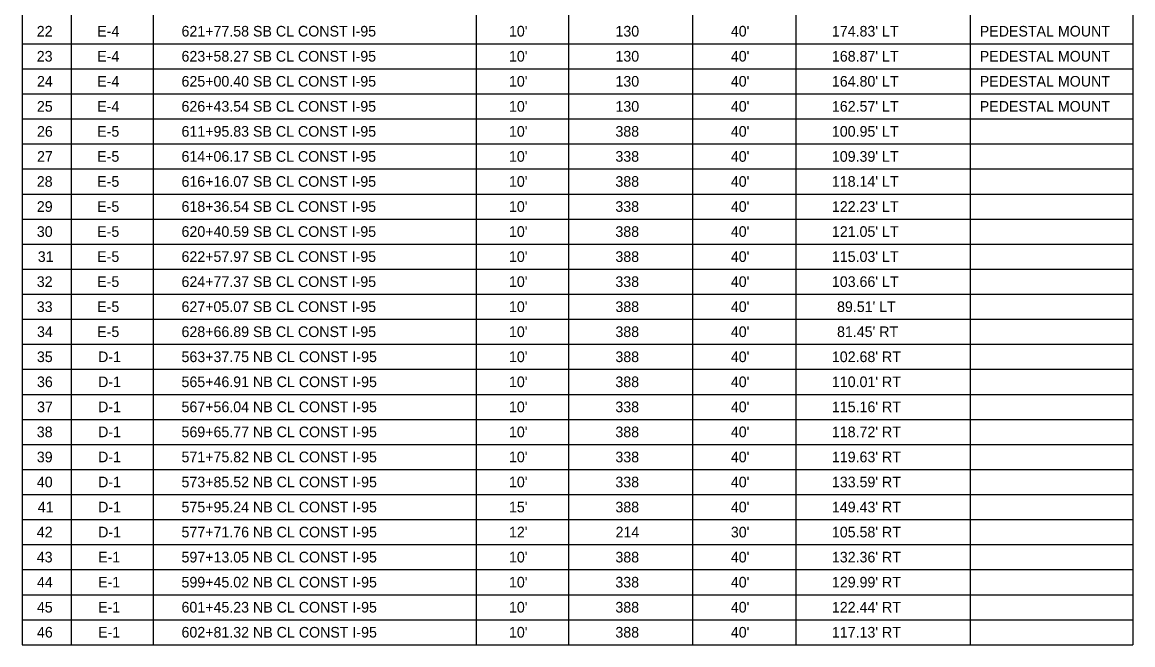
# Model space of a CAD drawing. Extents: x -818.1 to -802.4, y -2221.2 to -2187.7.
# Drawn here: x -817.38 to -810.06, y -2195.94 to -2191.84 of the extents above; entities that cross this region are included whole.
import ezdxf

# ---------------------------------------------------------------- set-up
doc = ezdxf.new("R2010")
doc.units = 0
for name, color, linetype in [('SumBoxBorder_dp', 7, 'Continuous'), ('SumBoxLines_dp', 7, 'Continuous'), ('SumBoxLinesMin_dp', 7, 'Continuous'), ('TextLabel', 7, 'Continuous')]:
    doc.layers.add(name, color=color, linetype=linetype)

msp = doc.modelspace()

# ---------------------------------------------------------------- linework, layer by layer
at = {"layer": 'SumBoxBorder_dp'}
for p, q in [((-817.3764, -2187.6917), (-817.3764, -2195.9417)), ((-810.0564, -2187.6917), (-810.0564, -2195.9417)), ((-810.0564, -2187.6917), (-810.0564, -2195.9417)), ((-817.3764, -2195.9417), (-817.0539, -2195.9417)), ((-817.0539, -2195.9417), (-810.0564, -2195.9417)), ((-816.5139, -2195.9417), (-814.3839, -2195.9417))]:
    msp.add_line(p, q, dxfattribs=at)
at = {"layer": 'SumBoxLines_dp'}
for p, q in [((-817.0539, -2188.0217), (-817.0539, -2195.9417)), ((-817.0539, -2188.0217), (-817.0539, -2195.9417)), ((-816.5139, -2188.0217), (-816.5139, -2195.9417)), ((-816.5139, -2188.0217), (-816.5139, -2195.9417)), ((-814.3839, -2188.0217), (-814.3839, -2193.9617)), ((-814.3839, -2188.0217), (-814.3839, -2195.9417)), ((-813.7764, -2188.0217), (-813.7764, -2195.9417)), ((-813.7764, -2188.0217), (-813.7764, -2195.9417)), ((-812.9589, -2188.0217), (-812.9589, -2195.9417)), ((-812.9589, -2188.0217), (-812.9589, -2195.9417)), ((-812.2764, -2188.0217), (-812.2764, -2195.9417)), ((-812.2764, -2188.0217), (-812.2764, -2195.9417)), ((-811.1289, -2188.0217), (-811.1289, -2195.9417)), ((-811.1289, -2188.0217), (-811.1289, -2195.9417)), ((-814.3839, -2194.1267), (-814.3839, -2195.9417))]:
    msp.add_line(p, q, dxfattribs=at)
at = {"layer": 'SumBoxLinesMin_dp'}
for p, q in [((-817.3764, -2191.9817), (-810.0564, -2191.9817)), ((-817.3764, -2191.9817), (-810.0564, -2191.9817)), ((-817.3764, -2192.1467), (-810.0564, -2192.1467)), ((-817.3764, -2192.1467), (-810.0564, -2192.1467)), ((-817.3764, -2192.3117), (-810.0564, -2192.3117)), ((-817.3764, -2192.3117), (-810.0564, -2192.3117)), ((-817.3764, -2192.4767), (-810.0564, -2192.4767)), ((-817.3764, -2192.4767), (-810.0564, -2192.4767)), ((-817.3764, -2192.6417), (-810.0564, -2192.6417)), ((-817.3764, -2192.6417), (-810.0564, -2192.6417)), ((-817.3764, -2192.8067), (-810.0564, -2192.8067)), ((-817.3764, -2192.8067), (-810.0564, -2192.8067)), ((-817.3764, -2192.9717), (-810.0564, -2192.9717)), ((-817.3764, -2192.9717), (-810.0564, -2192.9717)), ((-817.3764, -2193.1367), (-810.0564, -2193.1367)), ((-817.3764, -2193.1367), (-810.0564, -2193.1367)), ((-817.3764, -2193.3017), (-810.0564, -2193.3017)), ((-817.3764, -2193.3017), (-810.0564, -2193.3017)), ((-817.3764, -2193.4667), (-810.0564, -2193.4667)), ((-817.3764, -2193.4667), (-810.0564, -2193.4667)), ((-817.3764, -2193.6317), (-810.0564, -2193.6317)), ((-817.3764, -2193.6317), (-810.0564, -2193.6317)), ((-817.3764, -2193.7967), (-810.0564, -2193.7967)), ((-817.3764, -2193.7967), (-810.0564, -2193.7967)), ((-817.3764, -2193.9617), (-810.0564, -2193.9617)), ((-817.3764, -2193.9617), (-810.0564, -2193.9617)), ((-817.3764, -2194.1267), (-816.5139, -2194.1267)), ((-817.3764, -2194.1267), (-810.0564, -2194.1267)), ((-814.3839, -2194.1267), (-810.0564, -2194.1267)), ((-817.3764, -2194.2917), (-810.0564, -2194.2917)), ((-817.3764, -2194.2917), (-810.0564, -2194.2917)), ((-817.3764, -2194.4567), (-810.0564, -2194.4567)), ((-817.3764, -2194.4567), (-810.0564, -2194.4567)), ((-817.3764, -2194.6217), (-810.0564, -2194.6217)), ((-817.3764, -2194.6217), (-810.0564, -2194.6217)), ((-817.3764, -2194.7867), (-810.0564, -2194.7867)), ((-817.3764, -2194.7867), (-810.0564, -2194.7867)), ((-817.3764, -2194.9517), (-810.0564, -2194.9517)), ((-817.3764, -2194.9517), (-810.0564, -2194.9517)), ((-817.3764, -2195.1167), (-810.0564, -2195.1167)), ((-817.3764, -2195.1167), (-810.0564, -2195.1167)), ((-817.3764, -2195.2817), (-810.0564, -2195.2817)), ((-817.3764, -2195.2817), (-810.0564, -2195.2817)), ((-817.3764, -2195.4467), (-810.0564, -2195.4467)), ((-817.3764, -2195.4467), (-810.0564, -2195.4467)), ((-817.3764, -2195.6117), (-810.0564, -2195.6117)), ((-817.3764, -2195.6117), (-810.0564, -2195.6117)), ((-817.3764, -2195.7767), (-816.5139, -2195.7767)), ((-817.3764, -2195.7767), (-810.0564, -2195.7767)), ((-814.3839, -2195.7767), (-810.0564, -2195.7767)), ((-814.3839, -2195.9417), (-812.9589, -2195.9417)), ((-812.2764, -2195.9417), (-810.0564, -2195.9417))]:
    msp.add_line(p, q, dxfattribs=at)

# ---------------------------------------------------------------- texts
at = {"layer": 'TextLabel'}
for s, p in [('22', (-817.2804, -2191.9342)), ('E-4', (-816.8817, -2191.9342)), ('621+77.58 SB CL CONST I-95', (-816.3263, -2191.9342)), ("10'", (-814.1681, -2191.9342)), ('130', (-813.4662, -2191.9342)), ("40'", (-812.7056, -2191.9342)), ("174.83' LT", (-812.0396, -2191.9342)), ('PEDESTAL MOUNT', (-811.0651, -2191.9342)), ('23', (-817.2804, -2192.0992)), ('E-4', (-816.8817, -2192.0992)), ('623+58.27 SB CL CONST I-95', (-816.3263, -2192.0992)), ("10'", (-814.1681, -2192.0992)), ('130', (-813.4662, -2192.0992)), ("40'", (-812.7056, -2192.0992)), ("168.87' LT", (-812.0396, -2192.0992)), ('PEDESTAL MOUNT', (-811.0651, -2192.0992)), ('24', (-817.279, -2192.2642)), ('625+00.40 SB CL CONST I-95', (-816.3263, -2192.2642)), ("10'", (-814.1681, -2192.2642)), ('130', (-813.4662, -2192.2642)), ("40'", (-812.7056, -2192.2642)), ("164.80' LT", (-812.0396, -2192.2642)), ('PEDESTAL MOUNT', (-811.0651, -2192.2642)), ('E-4', (-816.8817, -2192.2642)), ('25', (-817.2795, -2192.4292)), ('E-4', (-816.8817, -2192.4292)), ('626+43.54 SB CL CONST I-95', (-816.3263, -2192.4292)), ("10'", (-814.1681, -2192.4292)), ('130', (-813.4662, -2192.4292)), ("40'", (-812.7056, -2192.4292)), ("162.57' LT", (-812.0396, -2192.4292)), ('PEDESTAL MOUNT', (-811.0651, -2192.4292)), ('26', (-817.279, -2192.5942)), ('E-5', (-816.8822, -2192.5942)), ('611+95.83 SB CL CONST I-95', (-816.3263, -2192.5942)), ("10'", (-814.1681, -2192.5942)), ('388', (-813.4665, -2192.5942)), ("40'", (-812.7056, -2192.5942)), ("100.95' LT", (-812.0396, -2192.5942)), ('27', (-817.2784, -2192.7592)), ('E-5', (-816.8822, -2192.7592)), ('614+06.17 SB CL CONST I-95', (-816.3263, -2192.7592)), ("10'", (-814.1681, -2192.7592)), ('338', (-813.4665, -2192.7592)), ("40'", (-812.7056, -2192.7592)), ("109.39' LT", (-812.0396, -2192.7592)), ('28', (-817.2802, -2192.9242)), ('E-5', (-816.8822, -2192.9242)), ('616+16.07 SB CL CONST I-95', (-816.3263, -2192.9242)), ("10'", (-814.1681, -2192.9242)), ('388', (-813.4665, -2192.9242)), ("40'", (-812.7056, -2192.9242)), ("118.14' LT", (-812.0396, -2192.9242)), ('29', (-817.28, -2193.0892)), ('E-5', (-816.8822, -2193.0892)), ('618+36.54 SB CL CONST I-95', (-816.3263, -2193.0892)), ("10'", (-814.1681, -2193.0892)), ('338', (-813.4665, -2193.0892)), ("40'", (-812.7056, -2193.0892)), ("122.23' LT", (-812.0396, -2193.0892)), ('30', (-817.2798, -2193.2542)), ('E-5', (-816.8822, -2193.2542)), ('620+40.59 SB CL CONST I-95', (-816.3263, -2193.2542)), ("10'", (-814.1681, -2193.2542)), ('388', (-813.4665, -2193.2542)), ("40'", (-812.7056, -2193.2542)), ("121.05' LT", (-812.0396, -2193.2542)), ('31', (-817.2737, -2193.4192)), ('E-5', (-816.8822, -2193.4192)), ('622+57.97 SB CL CONST I-95', (-816.3263, -2193.4192)), ("10'", (-814.1681, -2193.4192)), ('388', (-813.4665, -2193.4192)), ("40'", (-812.7056, -2193.4192)), ("115.03' LT", (-812.0396, -2193.4192)), ('32', (-817.2804, -2193.5842)), ('E-5', (-816.8822, -2193.5842)), ('624+77.37 SB CL CONST I-95', (-816.3263, -2193.5842)), ("10'", (-814.1681, -2193.5842)), ('338', (-813.4665, -2193.5842)), ("40'", (-812.7056, -2193.5842)), ("103.66' LT", (-812.0396, -2193.5842)), ('33', (-817.2804, -2193.7492)), ('E-5', (-816.8822, -2193.7492)), ('627+05.07 SB CL CONST I-95', (-816.3263, -2193.7492)), ("10'", (-814.1681, -2193.7492)), ('388', (-813.4665, -2193.7492)), ("40'", (-812.7056, -2193.7492)), ("89.51' LT", (-812.0057, -2193.7492)), ('34', (-817.279, -2193.9142)), ('E-5', (-816.8822, -2193.9142)), ('628+66.89 SB CL CONST I-95', (-816.3263, -2193.9142)), ("10'", (-814.1681, -2193.9142)), ('388', (-813.4665, -2193.9142)), ("40'", (-812.7056, -2193.9142)), ("81.45' RT", (-812.0057, -2193.9142)), ('35', (-817.2795, -2194.0792)), ('D-1', (-816.8763, -2194.0792)), ('563+37.75 NB CL CONST I-95', (-816.3263, -2194.0792)), ("10'", (-814.1681, -2194.0792)), ('388', (-813.4665, -2194.0792)), ("40'", (-812.7056, -2194.0792)), ("102.68' RT", (-812.0396, -2194.0792)), ('36', (-817.279, -2194.2442)), ('D-1', (-816.8763, -2194.2442)), ('565+46.91 NB CL CONST I-95', (-816.3263, -2194.2442)), ("10'", (-814.1681, -2194.2442)), ('388', (-813.4665, -2194.2442)), ("40'", (-812.7056, -2194.2442)), ("110.01' RT", (-812.0396, -2194.2442)), ('37', (-817.2784, -2194.4092)), ('D-1', (-816.8763, -2194.4092)), ('567+56.04 NB CL CONST I-95', (-816.3263, -2194.4092)), ("10'", (-814.1681, -2194.4092)), ('338', (-813.4665, -2194.4092)), ("40'", (-812.7056, -2194.4092)), ("115.16' RT", (-812.0396, -2194.4092)), ('38', (-817.2802, -2194.5742)), ('D-1', (-816.8763, -2194.5742)), ('569+65.77 NB CL CONST I-95', (-816.3263, -2194.5742)), ("10'", (-814.1681, -2194.5742)), ('388', (-813.4665, -2194.5742)), ("40'", (-812.7056, -2194.5742)), ("118.72' RT", (-812.0396, -2194.5742)), ('39', (-817.28, -2194.7392)), ('D-1', (-816.8763, -2194.7392)), ('571+75.82 NB CL CONST I-95', (-816.3263, -2194.7392)), ("10'", (-814.1681, -2194.7392)), ('338', (-813.4665, -2194.7392)), ("40'", (-812.7056, -2194.7392)), ("119.63' RT", (-812.0396, -2194.7392)), ('40', (-817.2798, -2194.9042)), ('D-1', (-816.8763, -2194.9042)), ('573+85.52 NB CL CONST I-95', (-816.3263, -2194.9042)), ("10'", (-814.1681, -2194.9042)), ('338', (-813.4665, -2194.9042)), ("40'", (-812.7056, -2194.9042)), ("133.59' RT", (-812.0396, -2194.9042)), ('41', (-817.2737, -2195.0692)), ('D-1', (-816.8763, -2195.0692)), ('575+95.24 NB CL CONST I-95', (-816.3263, -2195.0692)), ("15'", (-814.1681, -2195.0692)), ('388', (-813.4665, -2195.0692)), ("40'", (-812.7056, -2195.0692)), ("149.43' RT", (-812.0396, -2195.0692)), ('42', (-817.2804, -2195.2342)), ('D-1', (-816.8763, -2195.2342)), ('577+71.76 NB CL CONST I-95', (-816.3263, -2195.2342)), ("12'", (-814.1681, -2195.2342)), ('214', (-813.4654, -2195.2342)), ("30'", (-812.7056, -2195.2342)), ("105.58' RT", (-812.0396, -2195.2342)), ('43', (-817.2804, -2195.3992)), ('E-1', (-816.8763, -2195.3992)), ('597+13.05 NB CL CONST I-95', (-816.3263, -2195.3992)), ("10'", (-814.1681, -2195.3992)), ('388', (-813.4665, -2195.3992)), ("40'", (-812.7056, -2195.3992)), ("132.36' RT", (-812.0396, -2195.3992)), ('44', (-817.279, -2195.5642)), ('E-1', (-816.8763, -2195.5642)), ('599+45.02 NB CL CONST I-95', (-816.3263, -2195.5642)), ("10'", (-814.1681, -2195.5642)), ('338', (-813.4665, -2195.5642)), ("40'", (-812.7056, -2195.5642)), ("129.99' RT", (-812.0396, -2195.5642)), ('45', (-817.2795, -2195.7292)), ('E-1', (-816.8763, -2195.7292)), ('601+45.23 NB CL CONST I-95', (-816.3263, -2195.7292)), ("10'", (-814.1681, -2195.7292)), ('388', (-813.4665, -2195.7292)), ("40'", (-812.7056, -2195.7292)), ("122.44' RT", (-812.0396, -2195.7292)), ('46', (-817.279, -2195.8942)), ('E-1', (-816.8763, -2195.8942)), ('602+81.32 NB CL CONST I-95', (-816.3263, -2195.8942)), ("10'", (-814.1681, -2195.8942)), ('388', (-813.4665, -2195.8942)), ("40'", (-812.7056, -2195.8942)), ("117.13' RT", (-812.0396, -2195.8942))]:
    msp.add_text(s, height=0.07, dxfattribs=at).set_placement(p)

doc.saveas('drawing.dxf')
